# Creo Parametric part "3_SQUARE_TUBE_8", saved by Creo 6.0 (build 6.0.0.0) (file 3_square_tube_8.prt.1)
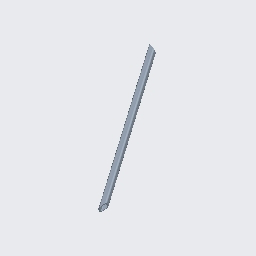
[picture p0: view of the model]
Units: Custom; MM, KILOGRAM, SECS
Materials in the file: STEEL

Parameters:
  BUW_NAME = "SQUARE TUBE"
  BUW_TYPE = "DIN EN 10219"
  BUW_SIZE = "25x25x3.0"
  BUW_LENGTH_STR = "705"
  PTC_MATERIAL_NAME = "STEEL"
  BUW_PROFIL_TYPE = "square_tube"
  BUW_PROFILE_PATH = "parts//profiles/steel_beams_mm/"
  BUW_PROFILE_NAME_LANG = "SQUARE TUBE"
  BUW_TAB_SEL_INFO = "-2 TYPE DIN_EN_10219-1997 SIZE_DINEN_10219 25x25x3.0"
  NAMING = "SQUARE TUBE"
  DESIGNATION = "DIN EN 10219 25x25x3.0 x 705"
  PROFIL_RASTER_POS = "X_0"
  BUW_OBJECT_ROLE = "PROFIL_SYSTEM_BORE_END_POINTS"
  PRO_UNIT_SYS = "Custom"

Other parameters: BUW_LENGTH, LENGTH, BUW_LENGTH_Z_MIN_PARAM, D8, D93, D94, d26, d8, d93, d94, d98, D98, SHEAR_MODULUS, THERM_EXPANSION_REF_TEMPERATURE, STRUCTURAL_DAMPING_COEFFICIENT, STRESS_LIMIT_FOR_TENSION, STRESS_LIMIT_FOR_COMPRESSION, STRESS_LIMIT_FOR_SHEAR, EMISSIVITY

Created from: SQUARE_TUBE.PRT

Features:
  1. datum plane "YZ"
  2. datum plane "XZ"
  3. datum plane "XY"
  4. coordinate system
  5. coordinate system
  6. coordinate system
  7. coordinate system
  8. datum plane "DTM3"
  9. datum plane "DTM4"
  10. datum plane "DTM5"
  11. protrusion
  12. round
  13. round
  14. datum axis
  15. datum point "PNT0"
  16. datum point

Other named items: PROFIL_CUT_QUILT, PROFILE_LENGTH_DIM, CONTACT_SURF_3, CONTACT_SURF_2, CONTACT_SURF_1, CONTACT_SURF_0, E, START_SURFACE, END_SURFACE, SIDE_SURF_3, SIDE_SURF_0, SIDE_SURF_1, SIDE_SURF_2, EDGE_7_S, EDGE_7_E, EDGE_1_S, EDGE_1_E, EDGE_3_S, EDGE_3_E, EDGE_5_S, EDGE_5_E, EDGE_6_S, EDGE_4_S, EDGE_2_S, EDGE_0_S, EDGE_6_E, EDGE_4_E, EDGE_2_E, EDGE_0_E, CS0, CS_S, CS_E, CS3

Named dimensions: X_ROT_S, Y_ROT_S, Z_OFF_S, X_ROT_E, Y_ROT_E, Z_OFF_E, PC_L, BUW_LENGTH_Z_MIN, BUW_LENGTH_DIM

Layers: 00_PROFIL_DATUM, 00_PROFIL_DRW_HIDE, 00_PROFIL_END_CSYS, 00_PROFIL_GEOMETRY, 00_PROFIL_QUILT, 00_PROFIL_SIZE_NOTE

Surfaces: 16 plane, 12 cylinder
